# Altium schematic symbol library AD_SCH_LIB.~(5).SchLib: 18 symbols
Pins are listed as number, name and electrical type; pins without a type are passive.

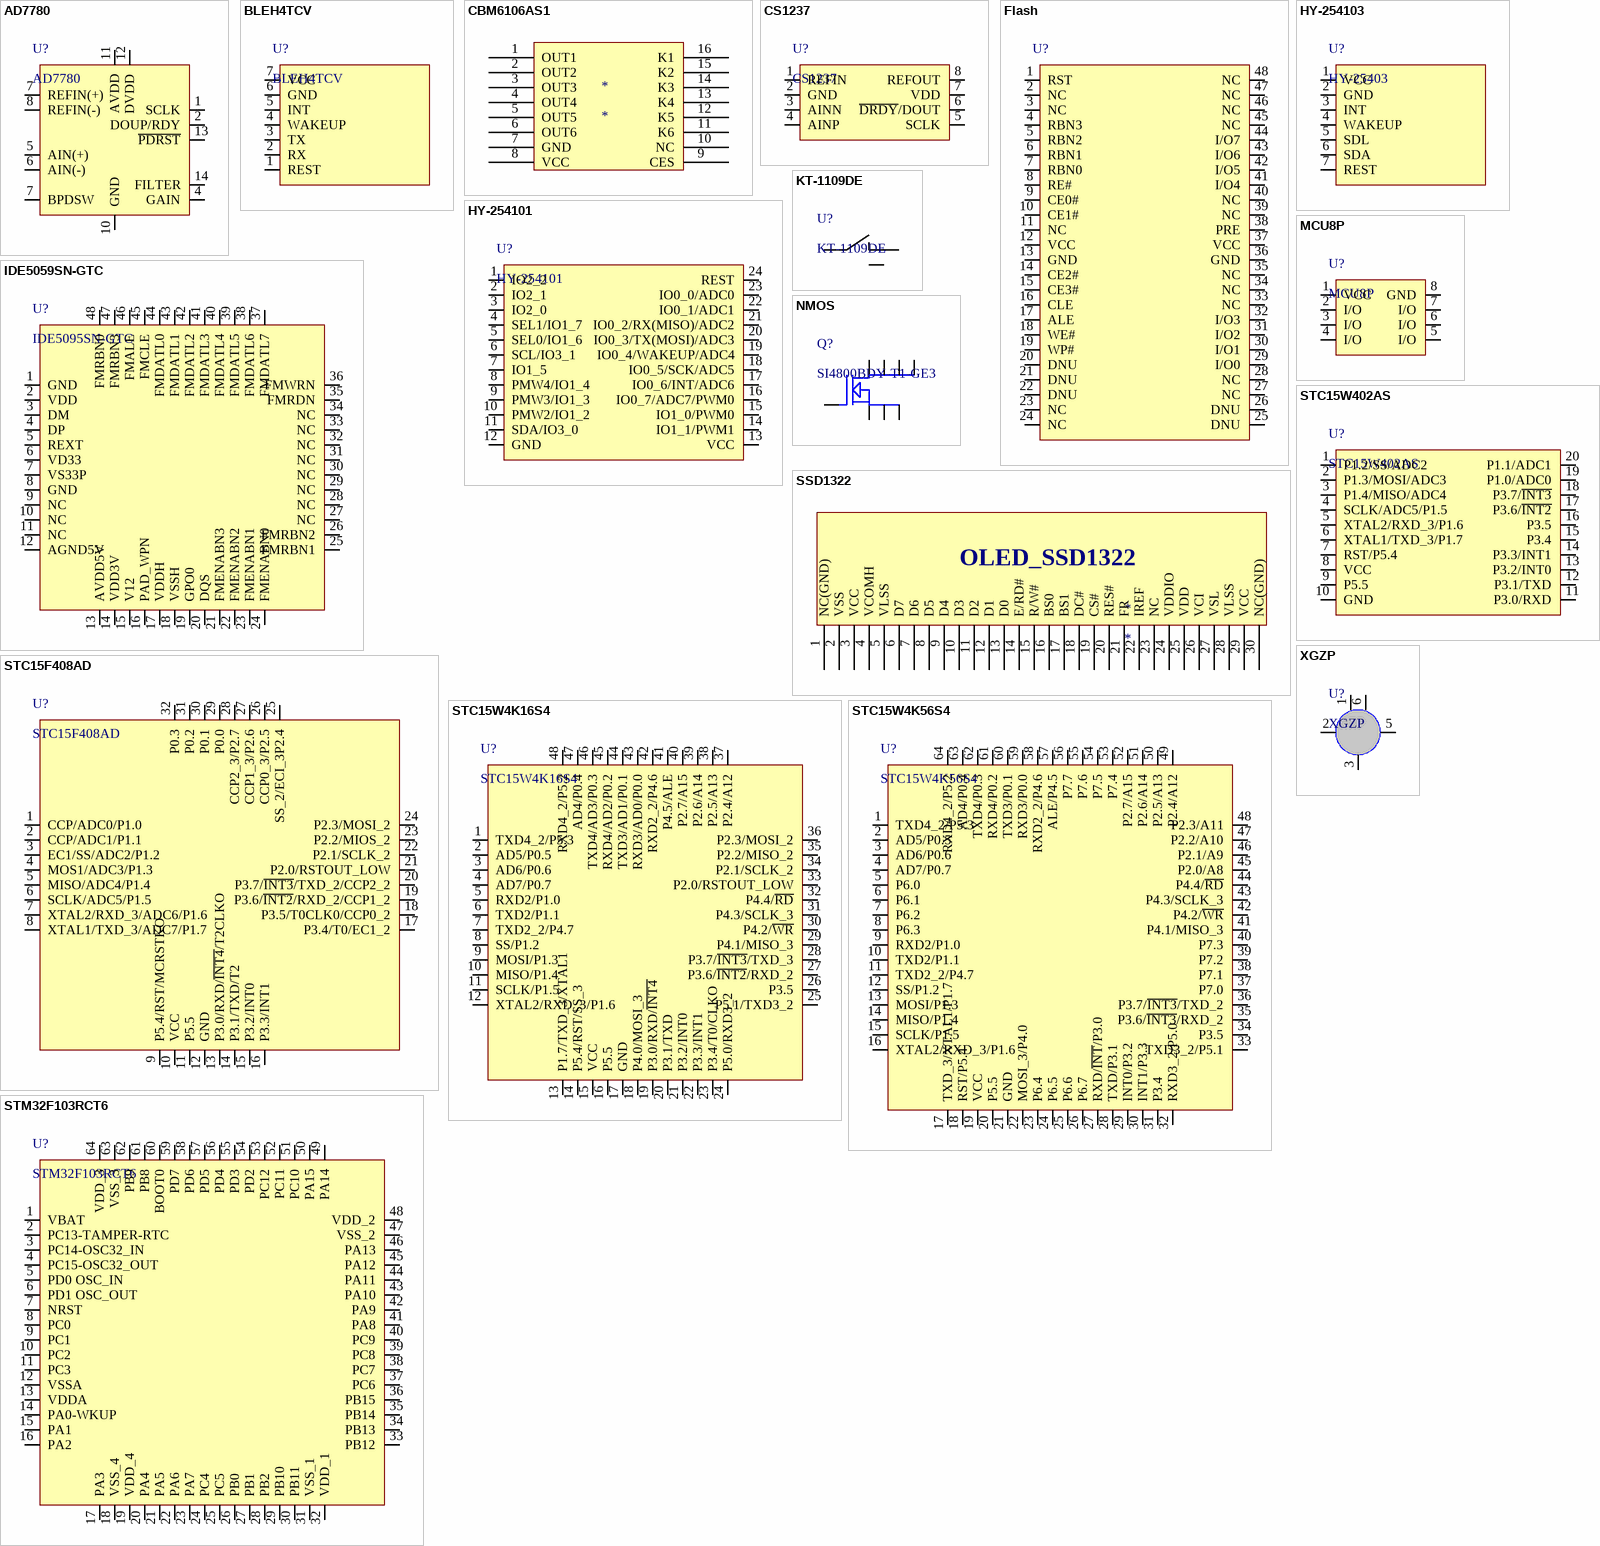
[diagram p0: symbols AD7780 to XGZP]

## AD7780
designator U?
footprint Model Name (Footprint not found)
pins: 1 SCLK, 2 DOUP/RDY, 4 GAIN, 5 AIN(+), 6 AIN(-), 7 REFIN(+), 7 BPDSW, 8 REFIN(-), 10 GND, 11 AVDD, 12 DVDD, 13 ~{PDRST}, 14 FILTER

## BLEH4TCV
designator U?
pins: 1 REST, 2 RX, 3 TX, 4 WAKEUP, 5 INT, 6 GND, 7 VCC

## CBM6106AS1
designator *
pins: 1 OUT1, 2 OUT2, 3 OUT3, 4 OUT4, 5 OUT5, 6 OUT6, 7 GND, 8 VCC, 9 CES, 10 NC, 11 K6, 12 K5, 13 K4, 14 K3, 15 K2, 16 K1

## CS1237
designator U?
footprint SO-8
pins: 1 REFIN, 2 GND, 3 AINN, 4 AINP, 5 SCLK, 6 ~{DRDY}/DOUT, 7 VDD, 8 REFOUT

## Flash
designator U?
pins: 1 RST, 2 NC, 3 NC, 4 RBN3, 5 RBN2, 6 RBN1, 7 RBN0, 8 RE#, 9 CE0#, 10 CE1#, 11 NC, 12 VCC, 13 GND, 14 CE2#, 15 CE3#, 16 CLE, 17 ALE, 18 WE#, 19 WP#, 20 DNU, 21 DNU, 22 DNU, 23 NC, 24 NC, 25 DNU, 26 DNU, 27 NC, 28 NC, 29 I/O0, 30 I/O1, 31 I/O2, 32 I/O3, 33 NC, 34 NC, 35 NC, 36 GND, 37 VCC, 38 PRE, 39 NC, 40 NC, 41 I/O4, 42 I/O5, 43 I/O6, 44 I/O7, 45 NC, 46 NC, 47 NC, 48 NC

## HY-254101
designator U?
pins: 1 IO2_2, 2 IO2_1, 3 IO2_0, 4 SEL1/IO1_7, 5 SEL0/IO1_6, 6 SCL/IO3_1, 7 IO1_5, 8 PMW4/IO1_4, 9 PMW3/IO1_3, 10 PMW2/IO1_2, 11 SDA/IO3_0, 12 GND, 13 VCC, 14 IO1_1/PWM1, 15 IO1_0/PWM0, 16 IO0_7/ADC7/PWM0, 17 IO0_6/INT/ADC6, 18 IO0_5/SCK/ADC5, 19 IO0_4/WAKEUP/ADC4, 20 IO0_3/TX(MOSI)/ADC3, 21 IO0_2/RX(MISO)/ADC2, 22 IO0_1/ADC1, 23 IO0_0/ADC0, 24 REST

## HY-254103
designator U?, comment HY-25403
pins: 1 VCC, 2 GND, 3 INT, 4 WAKEUP, 5 SDL, 6 SDA, 7 REST

## IDE5059SN-GTC
designator U?, comment IDE5095SN-GTC
pins: 1 GND, 2 VDD, 3 DM, 4 DP, 5 REXT, 6 VD33, 7 VS33P, 8 GND, 9 NC, 10 NC, 11 NC, 12 AGND5V, 13 AVDD5V, 14 VDD3V, 15 V12, 16 PAD_WPN, 17 VDDH, 18 VSSH, 19 GPO0, 20 DQS, 21 FMENABN3, 22 FMENABN2, 23 FMENABN1, 24 FMENABN0, 25 FMRBN1, 26 FMRBN2, 27 NC, 28 NC, 29 NC, 30 NC, 31 NC, 32 NC, 33 NC, 34 NC, 35 FMRDN, 36 FMWRN, 37 FMDATL7, 38 FMDATL6, 39 FMDATL5, 40 FMDATL4, 41 FMDATL3, 42 FMDATL2, 43 FMDATL1, 44 FMDATL0, 45 FMCLE, 46 FMALE, 47 FMRBN3, 48 FMRBN0

## KT-1109DE
designator U?
footprint KT-1109DE
pins: 1, 2, 3

## MCU8P
designator U?
pins: 1 VCC, 2 I/O, 3 I/O, 4 I/O, 5 I/O, 6 I/O, 7 I/O, 8 GND

## NMOS
designator Q?, comment SI4800BDY-T1-GE3
pins: 1 S, 2 S, 3 S, 4 G, 5 D, 6 D, 7 D, 8 D

## SSD1322
designator *
pins: 1 NC(GND), 2 VSS, 3 VCC, 4 VCOMH, 5 VLSS, 6 D7, 7 D6, 8 D5, 9 D4, 10 D3, 11 D2, 12 D1, 13 D0, 14 E/RD#, 15 R/W#, 16 BS0, 17 BS1, 18 DC#, 19 CS#, 20 RES#, 21 FR, 22 IREF, 23 NC, 24 VDDIO, 25 VDD, 26 VCI, 27 VSL, 28 VLSS, 29 VCC, 30 NC(GND)

## STC15F408AD
designator U?
footprint LQFP32
pins: 1 CCP/ADC0/P1.0, 2 CCP/ADC1/P1.1, 3 EC1/SS/ADC2/P1.2, 4 MOS1/ADC3/P1.3, 5 MISO/ADC4/P1.4, 6 SCLK/ADC5/P1.5, 7 XTAL2/RXD_3/ADC6/P1.6, 8 XTAL1/TXD_3/ADC7/P1.7, 9 P5.4/RST/MCRSTKO, 10 VCC, 11 P5.5, 12 GND, 13 P3.0/RXD/~{INT4}/T2CLKO, 14 P3.1/TXD/T2, 15 P3.2/INT0, 16 P3.3/INT1, 17 P3.4/T0/EC1_2, 18 P3.5/T0CLK0/CCP0_2, 19 P3.6/~{INT2}/RXD_2/CCP1_2, 20 P3.7/~{INT3}/TXD_2/CCP2_2, 21 P2.0/RSTOUT_LOW, 22 P2.1/SCLK_2, 23 P2.2/MIOS_2, 24 P2.3/MOSI_2, 25 SS_2/ECI_3P2.4, 26 CCP0_3/P2.5, 27 CCP1_3/P2.6, 28 CCP2_3/P2.7, 29 P0.0, 30 P0.1, 31 P0.2, 32 P0.3

## STC15W4K16S4
designator U?
pins: 1 TXD4_2/P5.3, 2 AD5/P0.5, 3 AD6/P0.6, 4 AD7/P0.7, 5 RXD2/P1.0, 6 TXD2/P1.1, 7 TXD2_2/P4.7, 8 SS/P1.2, 9 MOSI/P1.3, 10 MISO/P1.4, 11 SCLK/P1.5, 12 XTAL2/RXD_3/P1.6, 13 P1.7/TXD_3/XTAL1, 14 P5.4/RST/SS_3, 15 VCC, 16 P5.5, 17 GND, 18 P4.0/MOSI_3, 19 P3.0/RXD/~{INT4}, 20 P3.1/TXD, 21 P3.2/INT0, 22 P3.3/INT1, 23 P3.4/T0/CLKO, 24 P5.0/RXD3_2, 25 P5.1/TXD3_2, 26 P3.5, 27 P3.6/~{INT2}/RXD_2, 28 P3.7/~{INT3}/TXD_3, 29 P4.1/MISO_3, 30 P4.2/~{WR}, 31 P4.3/SCLK_3, 32 P4.4/~{RD}, 33 P2.0/RSTOUT_LOW, 34 P2.1/SCLK_2, 35 P2.2/MISO_2, 36 P2.3/MOSI_2, 37 P2.4/A12, 38 P2.5/A13, 39 P2.6/A14, 40 P2.7/A15, 41 P4.5/ALE, 42 RXD2_2/P4.6, 43 RXD3/AD0/P0.0, 44 TXD3/AD1/P0.1, 45 RXD4/AD2/P0.2, 46 TXD4/AD3/P0.3, 47 AD4/P0.4, 48 RXD4_2/P5.2

## STC15W4K56S4
designator U?
pins: 1 TXD4_2/P5.3, 2 AD5/P0.5, 3 AD6/P0.6, 4 AD7/P0.7, 5 P6.0, 6 P6.1, 7 P6.2, 8 P6.3, 9 RXD2/P1.0, 10 TXD2/P1.1, 11 TXD2_2/P4.7, 12 SS/P1.2, 13 MOSI/P1.3, 14 MISO/P1.4, 15 SCLK/P1.5, 16 XTAL2/RXD_3/P1.6, 17 TXD_3/XTAL1/P1.7, 18 RST/P5.4, 19 VCC, 20 P5.5, 21 GND, 22 MOSI_3/P4.0, 23 P6.4, 24 P6.5, 25 P6.6, 26 P6.7, 27 RXD/~{INT}/P3.0, 28 TXD/P3.1, 29 INT0/P3.2, 30 INT1/P3.3, 31 P3.4, 32 RXD3_2/P5.0, 33 TXD3_2/P5.1, 34 P3.5, 35 P3.6/~{INT3}/RXD_2, 36 P3.7/~{INT3}/TXD_2, 37 P7.0, 38 P7.1, 39 P7.2, 40 P7.3, 41 P4.1/MISO_3, 42 P4.2/~{WR}, 43 P4.3/SCLK_3, 44 P4.4/~{RD}, 45 P2.0/A8, 46 P2.1/A9, 47 P2.2/A10, 48 P2.3/A11, 49 P2.4/A12, 50 P2.5/A13, 51 P2.6/A14, 52 P2.7/A15, 53 P7.4, 54 P7.5, 55 P7.6, 56 P7.7, 57 ALE/P4.5, 58 RXD2_2/P4.6, 59 RXD3/P0.0, 60 TXD3/P0.1, 61 RXD4/P0.2, 62 TXD4/P0.3, 63 AD4/P0.4, 64 RXD4_2/P5.2

## STC15W402AS
designator U?
pins: 1 P1.2/SS/ADC2, 2 P1.3/MOSI/ADC3, 3 P1.4/MISO/ADC4, 4 SCLK/ADC5/P1.5, 5 XTAL2/RXD_3/P1.6, 6 XTAL1/TXD_3/P1.7, 7 RST/P5.4, 8 VCC, 9 P5.5, 10 GND, 11 P3.0/RXD, 12 P3.1/TXD, 13 P3.2/INT0, 14 P3.3/INT1, 15 P3.4, 16 P3.5, 17 P3.6/~{INT2}, 18 P3.7/~{INT3}, 19 P1.0/ADC0, 20 P1.1/ADC1

## STM32F103RCT6
designator U?
footprint LQFP64
pins: 1 VBAT, 2 PC13-TAMPER-RTC, 3 PC14-OSC32_IN, 4 PC15-OSC32_OUT, 5 PD0 OSC_IN, 6 PD1 OSC_OUT, 7 NRST, 8 PC0, 9 PC1, 10 PC2, 11 PC3, 12 VSSA, 13 VDDA, 14 PA0-WKUP, 15 PA1, 16 PA2, 17 PA3, 18 VSS_4, 19 VDD_4, 20 PA4, 21 PA5, 22 PA6, 23 PA7, 24 PC4, 25 PC5, 26 PB0, 27 PB1, 28 PB2, 29 PB10, 30 PB11, 31 VSS_1, 32 VDD_1, 33 PB12, 34 PB13, 35 PB14, 36 PB15, 37 PC6, 38 PC7, 39 PC8, 40 PC9, 41 PA8, 42 PA9, 43 PA10, 44 PA11, 45 PA12, 46 PA13, 47 VSS_2, 48 VDD_2, 49 PA14, 50 PA15, 51 PC10, 52 PC11, 53 PC12, 54 PD2, 55 PD3, 56 PD4, 57 PD5, 58 PD6, 59 PD7, 60 BOOT0, 61 PB8, 62 PB9, 63 VSS_3, 64 VDD_3

## XGZP
designator U?
pins: 1, 2, 3, 5, 6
